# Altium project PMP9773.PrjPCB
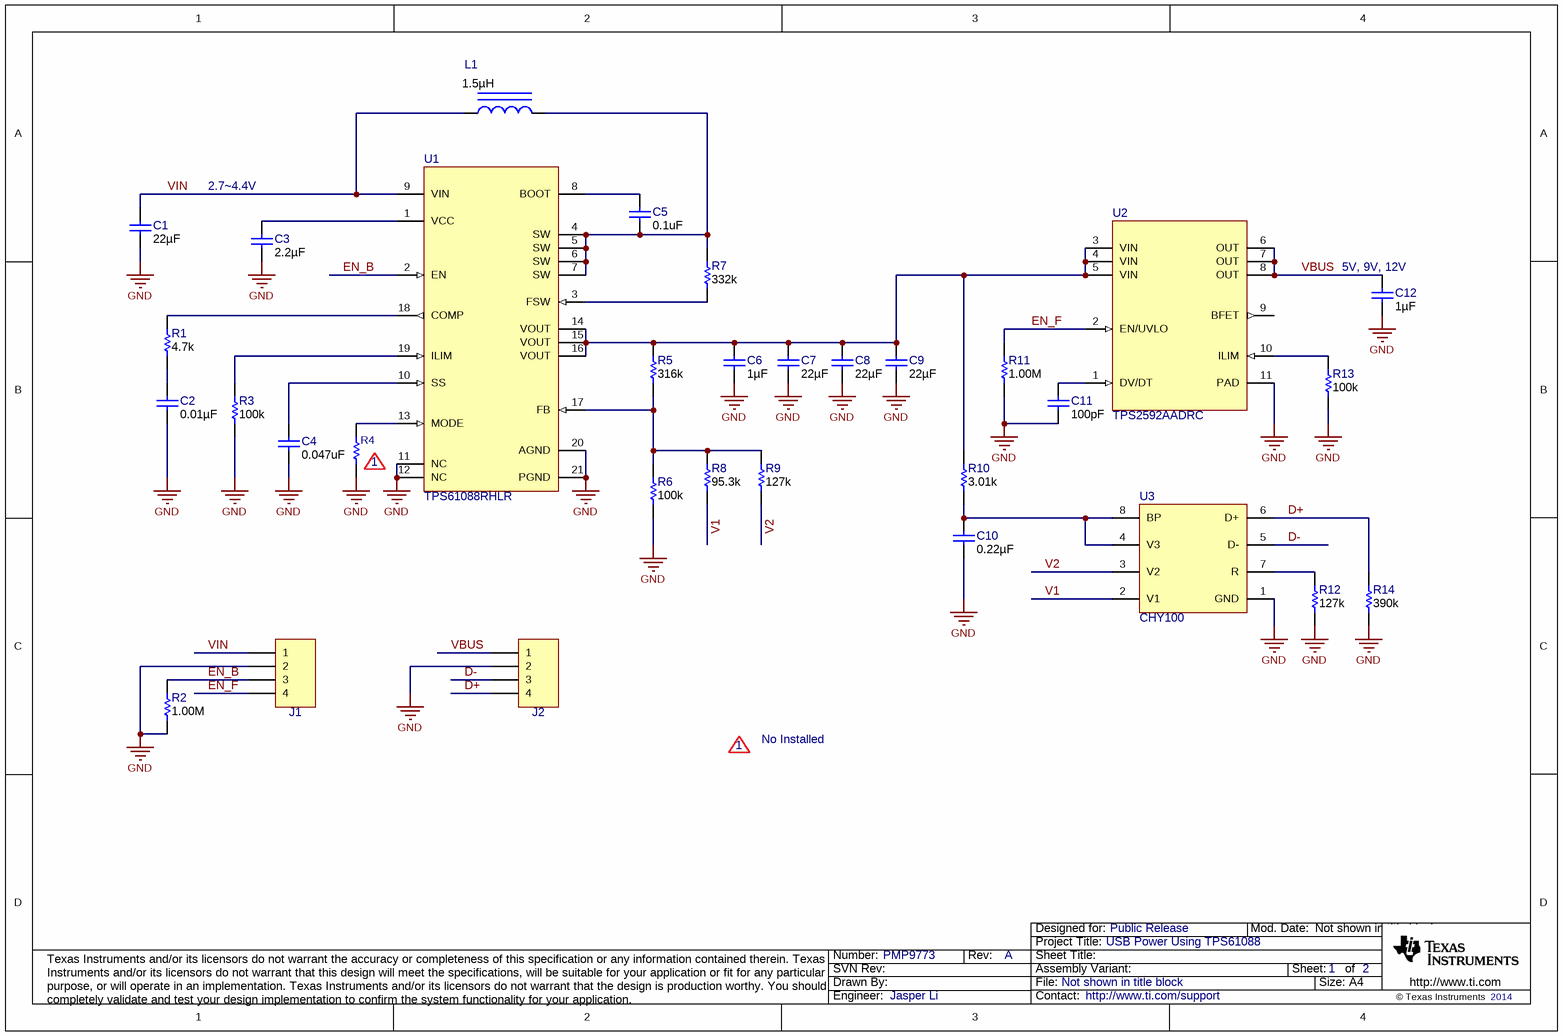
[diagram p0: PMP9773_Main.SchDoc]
TechSupport: http://www.ti.com/support; SCH_Rev: A; PRJ_Title: USB Power Using TPS61088; PRJ_Number: PMP9773; PRJ_Engineer: Jasper Li; PRJ_Customer: Public Release; PCB_Rev: A; PCB_Layout: Jasper Li; CopyrightYear: 2014
2 sheets, 37 parts. Net scope: global (net labels, ports and power ports of the same name join across sheets).
Board file: PMP9773.PcbDoc
Sheets:
  PMP9773_Main.SchDoc
  PMP9773_Hardware.SchDoc

## Sheet PMP9773_Main.SchDoc
size A4; Date: Not shown in title block; ApprovedBy: Not shown in title block; CheckedBy: Not shown in title block; Author: Not shown in title block; CompanyName: Not shown in title block; Engineer: Not shown in title block; Organization: Not shown in title block; Address1: Not shown in title block; Address2: Not shown in title block; Address3: Not shown in title block; Address4: Not shown in title block; DocumentNumber: 1; Revision: Use project parameter SCH_Rev; SheetNumber: 1; SheetTotal: 2; PageSetup: Record=PageOptions|CenterHorizontal=True|CenterVertical=True|PrintScale=0.91|XCorrection=1.00|YCorrection=1.00|PrintKind=0|BorderSize=5000000|LeftOffset=0|BottomOffset=0|Orientation=2|PaperLength=1000|PaperWidth=1000|Scale=100|PaperSource=15|PrintQuality=600|MediaType=1|DitherType=10|PaperKind=Letter|PrintScaleMode=1

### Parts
C1  ValueDisplayed: 22µF  [0603_100_HV]  (hidden comment: GRM188R61A226ME15D)
C2  ValueDisplayed: 0.01µF  [0402S]  (hidden comment: GRM155R71H103KA88D)
C3  ValueDisplayed: 2.2µF  [0402_70]  (hidden comment: GRM155R61E225KE11D)
C4  ValueDisplayed: 0.047uF  [0402S]  (hidden comment: GRM155R61A473KA01D)
C5  ValueDisplayed: 0.1uF  [0402S]  (hidden comment: GRM155R61C104KA88D)
C6  ValueDisplayed: 1µF  [0603S]  (hidden comment: GRM188R61E105KA12D)
C7  ValueDisplayed: 22µF  [0805L]  (hidden comment: GRM21BR61E226ME44)
C8  ValueDisplayed: 22µF  [0805L]  (hidden comment: GRM21BR61E226ME44)
C9  ValueDisplayed: 22µF  [0805L]  (hidden comment: GRM21BR61E226ME44)
C10  ValueDisplayed: 0.22µF  [0402S]  (hidden comment: GRM155R61A224KE19D)
C11  ValueDisplayed: 100pF  [0402S]  (hidden comment: GRM1535C1H101JDD5D)
C12  ValueDisplayed: 1µF  [0603S]  (hidden comment: GRM188R61E105KA12D)
J1  Connector  [Connector]  (value not drawn)
J2  Connector  [Connector]  (value not drawn)
L1  ValueDisplayed: 1.5µH  [WE-HC4]  (hidden comment: 744311150)
R1  ValueDisplayed: 4.7k  [0402S]  (hidden comment: CRCW04024K70JNED)
R2  ValueDisplayed: 1.00M  [0402S]  (hidden comment: CRCW04021M00FKED)
R3  value 100k  [0402S]  (hidden comment: CRCW0402100KFKED)
R4  RC0402JR-070RL  [0402s]  (value not drawn)
R5  ValueDisplayed: 316k  [0402S]  (hidden comment: CRCW0402316KFKED)
R6  ValueDisplayed: 100k  [0402S]  (hidden comment: CRCW0402100KFKED)
R7  ValueDisplayed: 332k  [0402S]  (hidden comment: CRCW0402332KFKED)
R8  ValueDisplayed: 95.3k  [0402S]  (hidden comment: CRCW040295K3FKED)
R9  ValueDisplayed: 127k  [0402S]  (hidden comment: CRCW0402127KFKED)
R10  ValueDisplayed: 3.01k  [0402S]  (hidden comment: CRCW04023K01FKED)
R11  ValueDisplayed: 1.00M  [0402S]  (hidden comment: CRCW04021M00FKED)
R12  ValueDisplayed: 127k  [0402S]  (hidden comment: CRCW0402127KFKED)
R13  value 100k  [0402S]  (hidden comment: CRCW0402100KFKED)
R14  ValueDisplayed: 390k  [0402S]  (hidden comment: CRCW0402390KJNED)
U1  TPS61088RHLR  [RHL0020A]
U2  TPS2592AADRC  [DRC0010J]
U3  CHY100  [CHY100]

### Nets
GND: C1.2 C2.2 C3.2 C4.2 C6.2 C7.2 C8.2 C9.2 C10.2 C11.2 C12.2 J1.2 J2.2 R2.1 R3.1 R4.2 R6.1 R11.1 R12.1 R13.1 R14.1 U1.11(NC) U1.12(NC) U1.20(AGND) U1.21(PGND) U2.11(PAD) U3.1(GND)
D+: J2.4 R14.2 U3.6(D+)
D-: J2.3 U3.5(D-)
EN_B: J1.3 R2.2 U1.2(EN)
EN_F: J1.4 R11.2 U2.2(EN/UVLO)
V1: R8.1 U3.2(V1)
V2: R9.1 U3.3(V2)
VBUS: C12.1 J2.1 U2.6(OUT) U2.7(OUT) U2.8(OUT)
VIN: C1.1 J1.1 L1.1 U1.9(VIN)
NetC2_1: C2.1 R1.1
NetC3_1: C3.1 U1.1(VCC)
NetC4_1: C4.1 U1.10(SS)
NetC5_1: C5.1 U1.8(BOOT)
NetC5_2: C5.2 L1.2 R7.2 U1.4(SW) U1.5(SW) U1.6(SW) U1.7(SW)
NetC6_1: C6.1 C7.1 C8.1 C9.1 R5.2 R10.2 U1.14(VOUT) U1.15(VOUT) U1.16(VOUT) U2.3(VIN) U2.4(VIN) U2.5(VIN)
NetC10_1: C10.1 R10.1 U3.4(V3) U3.8(BP)
NetC11_1: C11.1 U2.1(DV/DT)
NetR1_2: R1.2 U1.18(COMP)
NetR3_2: R3.2 U1.19(ILIM)
NetR4_1: R4.1 U1.13(MODE)
NetR5_1: R5.1 R6.2 R8.2 R9.2 U1.17(FB)
NetR7_1: R7.1 U1.3(FSW)
NetR12_2: R12.2 U3.7(R)
NetR13_2: R13.2 U2.10(ILIM)

Not connected (* = marked no-connect by the designer): U2 9(BFET)

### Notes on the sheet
- (near C3) 2.7~4.4V
- (near C12) 5V, 9V, 12V
- (near R4) 1
- 1
- No Installed

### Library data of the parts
C1 = GRM188R61A226ME15D: CAP, CERM, 22 µF, 10 V, +/- 20%, X5R, 0603; Manufacturer: MuRata; Polarized: N; CompType: Capacitor; Value: 22uF; U/M: EA; Cap_F: 0.000022; Tolerance_%: 20; Value1: Unknown; VDC_V: 10; Value2: 10V; TaMin_C: -55; TaMax_C: 85; Cap_Case: 0603
C2 = GRM155R71H103KA88D: CAP, CERM, 0.01 µF, 50 V, +/- 10%, X7R, 0402; Manufacturer: MuRata; Polarized: N; CompType: Capacitor; Value: 0.01uF; U/M: EA; Cap_F: 0.00000001; Tolerance_%: 10; Value1: Unknown; VDC_V: 50; Value2: 50V; TaMin_C: -55; TaMax_C: 125; Cap_Case: 0402
C3 = GRM155R61E225KE11D: CAP, CERM, 2.2 µF, 25 V, +/- 10%, X5R, 0402; Manufacturer: MuRata; Polarized: N; CompType: Capacitor; Value: 2.2uF; U/M: EA; Cap_F: 0.0000022; Tolerance_%: 10; Value1: Unknown; VDC_V: 25; Value2: 25V; TaMin_C: -55; TaMax_C: 85; Cap_Case: 0402
C4 = GRM155R61A473KA01D: CAP, CERM, 0.047uF, 10V, +/-10%, X5R, 0402; Manufacturer: MuRata; Polarized: N; CompType: Capacitor; U/M: EA; Cap_F: 0.000000047; Tolerance_%: 10; Value1: Unknown; TaMin_C: -55; TaMax_C: 85; Cap_Case: 0402
C5 = GRM155R61C104KA88D: CAP, CERM, 0.1uF, 16V, +/-10%, X5R, 0402; Manufacturer: MuRata; Polarized: N; CompType: Capacitor; U/M: EA; Cap_F: 0.0000001; Tolerance_%: 10; Value1: Unknown; VDC_V: 16; TaMin_C: -55; TaMax_C: 85; Cap_Case: 0402
C6 C12 = GRM188R61E105KA12D: CAP, CERM, 1 µF, 25 V, +/- 10%, X5R, 0603; Manufacturer: MuRata; Polarized: N; CompType: Capacitor; Value: 1uF; U/M: EA; Cap_F: 0.000001; Tolerance_%: 10; Value1: Unknown; VDC_V: 25; Value2: 25V; TaMin_C: -55; TaMax_C: 85; Cap_Case: 0603
C7-C9 = GRM21BR61E226ME44: CAP, CERM, 22 µF, 25 V, +/- 20%, X5R, 0805; Manufacturer: MuRata; Polarized: N; CompType: Capacitor; Value: 22uF; U/M: EA; Cap_F: 0.000022; Tolerance_%: 20; Value1: Unknown; VDC_V: 25; Value2: 25V; TaMin_C: -55; TaMax_C: 85; Cap_Case: 0805
C10 = GRM155R61A224KE19D: CAP, CERM, 0.22 µF, 10 V, +/- 10%, X5R, 0402; Manufacturer: MuRata; Polarized: N; CompType: Capacitor; Value: 0.22uF; U/M: EA; Cap_F: 0.00000022; Tolerance_%: 10; Value1: Unknown; Value2: 10V; TaMin_C: -55; TaMax_C: 85; Cap_Case: 0402
C11 = GRM1535C1H101JDD5D: CAP, CERM, 100 pF, 50 V, +/- 5%, C0G/NP0, 0402; Manufacturer: MuRata; Polarized: N; CompType: Capacitor; Value: 100pF; U/M: EA; Cap_F: 0.0000000001; Tolerance_%: 5; Value1: Unknown; VDC_V: 50; Value2: 50V; TaMin_C: -55; TaMax_C: 125; Cap_Case: 0402
J1 J2 = Connector: Manufacturer: Used in BOM report; SymbolVersion: use current date i.e. 2008-05-20; SymbolCreator: Use a-id; CompType: Used in some BOM reports.  Useful for finding later.; U/M: EA, IN, or GM
L1 = 744311150: Inductor, Shielded Drum Core, Superflux, 1.5 µH, 11 A, 0.0078 ohm, SMD; Manufacturer: Wurth Elektronik eiSos; Value: 1.5uH; Ind_H: 1.5E-6; Imax_A: 11; Irms: 11A @ 50C rise; Isat: 14A @ 30% inductance drop; DCR_ohm: 0.0078; Value2: 11A
R1 = CRCW04024K70JNED: RES, 4.7 k, 5%, 0.063 W, 0402; Manufacturer: Vishay-Dale; CompType: Resistor; Value: 4.7k; Res_ohm: 4700; Value_Code: 4k70; Tolerance_%: 5; Power_W: 0.063; Value2: 0.063W; VDC_V: 50; TempCo: 200 ppm/C; EIA_Code: E24; U/M: EA
R2 R11 = CRCW04021M00FKED: RES, 1.00 M, 1%, 0.063 W, 0402; Manufacturer: Vishay-Dale; CompType: Resistor; Value: 1.00Meg; Res_ohm: 1000000; Value_Code: 1M00; Tolerance_%: 1; Power_W: 0.063; Value2: 0.063W; VDC_V: 50; TempCo: 100 ppm/C; EIA_Code: E96; U/M: EA
R3 R13 = CRCW0402100KFKED: RES, 100k ohm, 1%, 0.063W, 0402; Manufacturer: Vishay-Dale; CompType: Resistor; Res_ohm: 100000; Tolerance_%: 1; Power_W: 0.063; VDC_V: 50; TempCo: 100 ppm/C; EIA_Code: E96; U/M: EA
R4 = RC0402JR-070RL: RES, 0 ohm, 5%, 0.063W, 0402; Manufacturer: Yageo America; CompType: Resistor; Value: 0; Value_Code: 0000; Tolerance_%: 5; Power_W: 0.063; VDC_V: 50; TempCo: 200 ppm/C; EIA_Code: E24; U/M: EA
R5 = CRCW0402316KFKED: RES, 316 k, 1%, 0.063 W, 0402; Manufacturer: Vishay-Dale; CompType: Resistor; Value: 316k; Res_ohm: 316000; Tolerance_%: 1; Power_W: 0.063; Value2: 0.063W; VDC_V: 50; TempCo: 100 ppm/C; EIA_Code: E96; U/M: EA
R6 = CRCW0402100KFKED: RES, 100 k, 1%, 0.063 W, 0402; Manufacturer: Vishay-Dale; CompType: Resistor; Value: 100k; Res_ohm: 100000; Tolerance_%: 1; Power_W: 0.063; Value2: 0.063W; VDC_V: 50; TempCo: 100 ppm/C; EIA_Code: E96; U/M: EA
R7 = CRCW0402332KFKED: RES, 332 k, 1%, 0.063 W, 0402; Manufacturer: Vishay-Dale; CompType: Resistor; Value: 332k; Res_ohm: 332000; Tolerance_%: 1; Power_W: 0.063; Value2: 0.063W; VDC_V: 50; TempCo: 100 ppm/C; EIA_Code: E96; U/M: EA
R8 = CRCW040295K3FKED: RES, 95.3 k, 1%, 0.063 W, 0402; Manufacturer: Vishay-Dale; CompType: Resistor; Value: 95.3k; Res_ohm: 95300; Value_Code: 95k3; Tolerance_%: 1; Power_W: 0.063; Value2: 0.063W; VDC_V: 50; TempCo: 100 ppm/C; EIA_Code: E96; U/M: EA
R9 R12 = CRCW0402127KFKED: RES, 127 k, 1%, 0.063 W, 0402; Manufacturer: Vishay-Dale; CompType: Resistor; Value: 127k; Res_ohm: 127000; Tolerance_%: 1; Power_W: 0.063; Value2: 0.063W; VDC_V: 50; TempCo: 100 ppm/C; EIA_Code: E96; U/M: EA
R10 = CRCW04023K01FKED: RES, 3.01 k, 1%, 0.063 W, 0402; Manufacturer: Vishay-Dale; CompType: Resistor; Value: 3.01k; Res_ohm: 3010; Value_Code: 3k01; Tolerance_%: 1; Power_W: 0.063; Value2: 0.063W; VDC_V: 50; TempCo: 100 ppm/C; EIA_Code: E96; U/M: EA
R14 = CRCW0402390KJNED: RES, 390 k, 5%, 0.063 W, 0402; Manufacturer: Vishay-Dale; CompType: Resistor; Value: 390k; Res_ohm: 390000; Tolerance_%: 5; Power_W: 0.063; Value2: 0.063W; VDC_V: 50; TempCo: 200 ppm/C; EIA_Code: E24; U/M: EA
U1 = TPS61088RHLR: 13.2-V Output, Synchronous Boost Converter with 10-A Switch, RHL0020A; Alternate PartNumber: TPS61088RHLT; Manufacturer: Texas Instruments; SymbolCreator: Altium; CompType: IC; U/M: EA
U2 = TPS2592AADRC: 12V eFuse with Integrated Blocking FET Driver, Auto Retry, DRC0010J; Manufacturer: Texas Instruments; SymbolCreator: a0799628; CompType: IC; U/M: EA
U3 = CHY100: Manufacturer: Used in BOM report; SymbolVersion: use current date i.e. 2008-05-20; SymbolCreator: Use a-id; CompType: Used in some BOM reports.  Useful for finding later.; U/M: EA, IN, or GM

## Sheet PMP9773_Hardware.SchDoc
size A4; Date: Not shown in title block; ApprovedBy: Not shown in title block; CheckedBy: Not shown in title block; Author: Not shown in title block; CompanyName: Not shown in title block; Engineer: Not shown in title block; Organization: Not shown in title block; Address1: Not shown in title block; Address2: Not shown in title block; Address3: Not shown in title block; Address4: Not shown in title block; DocumentNumber: 2; Revision: Use project parameter SCH_Rev; SheetNumber: 2; SheetTotal: 2; PageSetup: Record=PageOptions|CenterHorizontal=True|CenterVertical=True|PrintScale=1.00|XCorrection=1.00|YCorrection=1.00|PrintKind=0|BorderSize=5000000|LeftOffset=0|BottomOffset=0|Orientation=2|PaperLength=1000|PaperWidth=1000|Scale=100|PaperSource=15|PrintQuality=600|MediaType=1|DitherType=10|PaperKind=Letter|PrintScaleMode=1
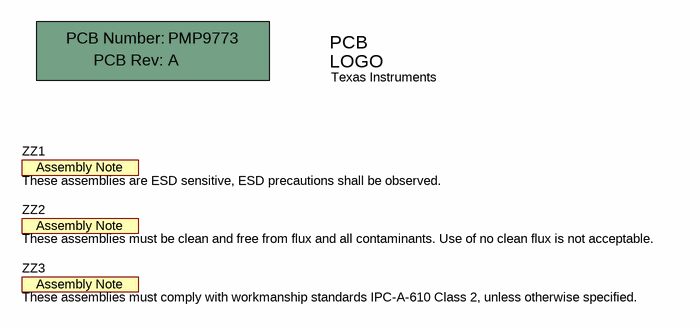
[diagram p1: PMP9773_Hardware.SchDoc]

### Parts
!PCB1  Printed Circuit Board  (value not drawn)  (mechanical)
Logo1  Texas Instruments  [TI_Stacked_Overlay_Small]  (no BOM)
ZZ1  These assemblies are ESD sensitive, ESD precautions shall be observed.  [AssemblyNote]  (no BOM)
ZZ2  These assemblies must be clean and free from flux and all contaminants. Use of no clean flux is not acceptable.  [AssemblyNote]  (no BOM)
ZZ3  These assemblies must comply with workmanship standards IPC-A-610 Class 2, unless otherwise specified.  [AssemblyNote]  (no BOM)

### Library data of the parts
!PCB1 = PCB: Manufacturer: Any; PartNumber: PMP9773; SymbolCreator: a0412235
Logo1 = TI_Logo: Texas Instrument Corporate Signature; SymbolCreator: a0412235
ZZ1-ZZ3 = AssemblyNote: SymbolCreator: codlsc

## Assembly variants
001: not fitted D1 R4 R10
